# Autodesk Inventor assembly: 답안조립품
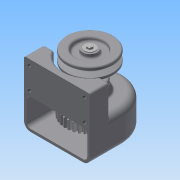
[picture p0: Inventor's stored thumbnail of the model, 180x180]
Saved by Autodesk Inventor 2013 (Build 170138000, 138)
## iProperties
Created: 2015-02
Part Number: 답안조립품
Document SubType Name: Assembly
Designer: Administrator
Author: Administrator
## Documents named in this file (14)
- C:\Documents and Settings\Administrator\바탕 화면\450214V1019\답안조립품.iam
- C:\Documents and Settings\Administrator\바탕 화면\450214V1019\1-본체.ipt
- C:\Documents and Settings\Administrator\바탕 화면\450214V1019\베어링 6001.ipt
- C:\Documents and Settings\Administrator\바탕 화면\450214V1019\축.ipt
- C:\Documents and Settings\Administrator\바탕 화면\450214V1019\4-v벨트풀리.ipt
- C:\Documents and Settings\Administrator\바탕 화면\450214V1019\5-스퍼기어.ipt
- C:\Documents and Settings\Administrator\바탕 화면\450214V1019\키5x5.ipt
- C:\Documents and Settings\Administrator\바탕 화면\450214V1019\키4x4.ipt
- C:\Documents and Settings\Administrator\바탕 화면\450214V1019\축커버.ipt
- C:\Documents and Settings\Administrator\바탕 화면\450214V1019\오일실.ipt
- C:\Documents and Settings\Administrator\바탕 화면\450214V1019\M3x0.5.ipt
- C:\Documents and Settings\Administrator\바탕 화면\450214V1019\와샤.ipt
- C:\Documents and Settings\Administrator\바탕 화면\450214V1019\M5x0.8.ipt
- M5x0.8.ipt
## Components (7 placed, 4 different names)
1. 1-본체:1
2. 4-v벨트풀리:1 — 플러쉬:1, 각도:4
3. M5x0.8:1 — 각도:5
4. M3x0.5:1
5. M3x0.5:2
6. M3x0.5:3
7. M3x0.5:4
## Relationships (3: Angle 2, Flush 1)
- 플러쉬:1 [Flush]: 4-v벨트풀리:1
- 각도:4 [Angle]: 4-v벨트풀리:1
- 각도:5 [Angle]: M5x0.8:1
